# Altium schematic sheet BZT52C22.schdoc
size 127 x 101 mm
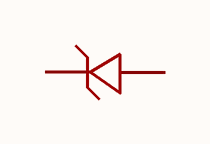
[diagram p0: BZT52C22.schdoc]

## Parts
D?  bzt52c22_c173423  [SOD-123_L2.7-W1.6-LS3.7-RD]  (value not drawn)

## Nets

Not connected (* = marked no-connect by the designer): D? 1(K) 2(A)

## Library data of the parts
D? = bzt52c22_c173423: 二极管配置:1个独立式;稳压值(标称值):22V;稳压值(范围):20.9V~23.1V;耗散功率(Pd):500mW;; Manufacturer: MDD(辰达半导体); AddInBom: yes; ModelId: ad7e39f9e5534b3c96ffdc5532ebb493; ModelName: SOD-123_L2.7-W1.6-H1.4-LS3.7; ModelTransform: 146.026,62.992,0,180,0,0,0.0005,0,0; Diode Configuration: 1个独立式; Zener Voltage(Nom): 22V; Reverse Leakage Current (Ir): 100nA; Pd - Power Dissipation: 500mW; Impedance(Zzt): 55Ω; Tolerance: ±5%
